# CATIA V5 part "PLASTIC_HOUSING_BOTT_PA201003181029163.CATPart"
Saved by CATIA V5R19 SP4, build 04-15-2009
Part number: PLASTIC_HOUSING_BOTT_PA201003181029163
Bounding box of the stored display mesh (mm): x -26 to 26, y -20.64 to 95, z 0 to 11
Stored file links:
  E:\CadInnWork\InWork\PLASTIC_HOUSING_BOTT_PA201003181029163.CATPart
  C:\Documents and Settings\moren\Bureau\3D models\Lampe\CATIA_V5\plastic_housing_up.CATPart
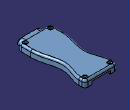
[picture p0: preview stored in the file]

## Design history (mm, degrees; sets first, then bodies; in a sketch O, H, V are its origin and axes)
Parameters
  Update = false
  PDM_version = "A"
  PDM_iteration = 1
  PDM_owner = "moren                    "
  PDM_comment = ""
  PDM_partnumber = "PA002170EA6A57201003181029160003"
Body1 (main body)
  Body2
    Solid1: solid without history
    Sketch1 on xy-plane, origin (0, 0, 0), H (1, 0, 0), V (0, 1, 0)
      line L1 (-40.7243, 108.5502) -> (41.8092, 108.5502)
      line L2 (41.8092, 108.5502) -> (41.8092, -35.0377)
      line L3 (41.8092, -35.0377) -> (-40.7243, -35.0377)
      line L4 (-40.7243, -35.0377) -> (-40.7243, 108.5502)
      horizontal: L1 H, L3 H
      vertical: L2 V, L4 V
    Pocket1: profile Sketch1, direction (0, 0, -1), through (limit type 3)
    Sketch2 on face of Solid1, origin (-15.025, 0, 0), H (0, 1, 0), V (0, 0, 1)
      point P1 (95, 0)
      line L1 (95, 0) -> (93.875, 0)
      line L2 (93.875, 0) -> (93.875, 0.75)
      line L3 (93.875, 0.75) -> (95, 0.75)
      line L4 (95, 0.75) -> (95, 0)
      reference projected point E1 (95, 0) from Sketch3.P17
      reference projected line E2 (93, 0) -> (93, 5.525) from edge [face of Solid1 | face of Solid1]
      length L4 = 0.75
      distance L2 E2 = 0.875
      horizontal: L1 H, L3 H
      vertical: L2 V, L4 V
      coincidence: P1 E1
    Sketch3 on xy-plane, origin (0, 0, 0), H (1, 0, 0), V (0, 1, 0)
      projected line E1 (-18.9, -12.64) -> (-18.9, -19.64) from edge [face of Solid1 | face of Solid1]
      projected arc E2 centre (-19.4001, -12.6401) radius 0.5001 from (-18.9, -12.64) to (-19.4, -12.14) ccw from edge [face of Solid1 | face of Solid1]
      projected line E3 (-19.4, -12.14) -> (-21, -12.14) from edge [face of Solid1 | face of Solid1]
      projected arc E4 centre (-21, -7.14) radius 5 from (-26, -7.14) to (-21, -12.14) ccw from edge [face of Solid1 | face of Solid1]
      projected line E5 (-26, 8.6583) -> (-26, -7.14) from edge [face of Solid1 | face of Solid1]
      projected curve E6 from edge [face of Solid1 | face of Solid1]
      projected line E7 (-26, 90) -> (-26, 85.2347) from edge [face of Solid1 | face of Solid1]
      projected arc E8 centre (-21, 90) radius 5 from (-21, 95) to (-26, 90) ccw from edge [face of Solid1 | face of Solid1]
      projected line E9 (-15.025, 95) -> (-21, 95) from edge [face of Solid1 | face of Solid1]
      point P17 (-15.025, 95)
      line L1 (-18.9, -19.64) -> (-18.9, -22.3506)
      tangency: L1 E2
    Slot1: profile Sketch2, centre curve Sketch3
    Mirror1: of Slot1, about yz-plane
    Point1: type Center, Curve edge [face of Solid1 | face of Solid1]
    Plane1: type OffsetPt, RefPlane yz-plane, RefPoint Point1
    Sketch4 on face of Solid1, origin (20.4668, -2.0655, 11), H (1, 0, 0), V (0, 1, 0)
      point P1 (-0.4668, -4.0745)
      reference projected point E1 (-0.4668, -4.0745) from Point1
      coincidence: P1 E1
    Hole1: placed by Sketch4, at (20, -6.14, 11) direction (0, 0, -1), diameter 6, depth 3
    Sketch5 on face of Hole1, origin (0, 0, 8), H (1, 0, 0), V (0, 1, 0)
      circle A1 centre (20, -6.14) radius 2
      point P1 (20, -6.14)
      reference projected point E1 (20, -6.14) from Point1
      projected circle E2 centre (20, -6.14) radius 2.4 from edge [face of Solid1 | face of Hole1]
      radius A1 = 2
      coincidence: P1 E1
    Pad1: profile Sketch5, direction (0, 0, -1), up to face of Solid1
    Mirror2: of Hole1, Pad1, about yz-plane
    Point2: type Center, Curve edge [face of Solid1 | face of Solid1]
    Sketch6 on face of Solid1, origin (16.6497, 85.0207, 11), H (1, 0, 0), V (0, 1, 0)
      point P1 (3.3503, 3.9793)
      reference projected point E1 (3.3503, 3.9793) from Point2
      coincidence: P1 E1
    Hole2: placed by Sketch6, at (20, 89, 11) direction (0, 0, -1), diameter 6, depth 3
    Sketch7 on face of Hole2, origin (0, 0, 8), H (1, 0, 0), V (0, 1, 0)
      circle A1 centre (20, 89) radius 2
      point P1 (20, 89)
      reference projected point E1 (20, 89) from Point2
      projected circle E2 centre (20, 89) radius 2.4 from edge [face of Solid1 | face of Hole2]
      radius A1 = 2
      coincidence: P1 E1
    Pad2: profile Sketch7, direction (0, 0, -1), up to face of Solid1
    Mirror3: of Hole2, Pad2, about yz-plane
    Fillet1: radius 0.5, on edge [face of Hole2 | face of Solid1]; edge [face of Mirror3 | face of Solid1]; edge [face of Mirror2 | face of Solid1]; edge [face of Hole1 | face of Solid1]
  Add1: tool Body2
